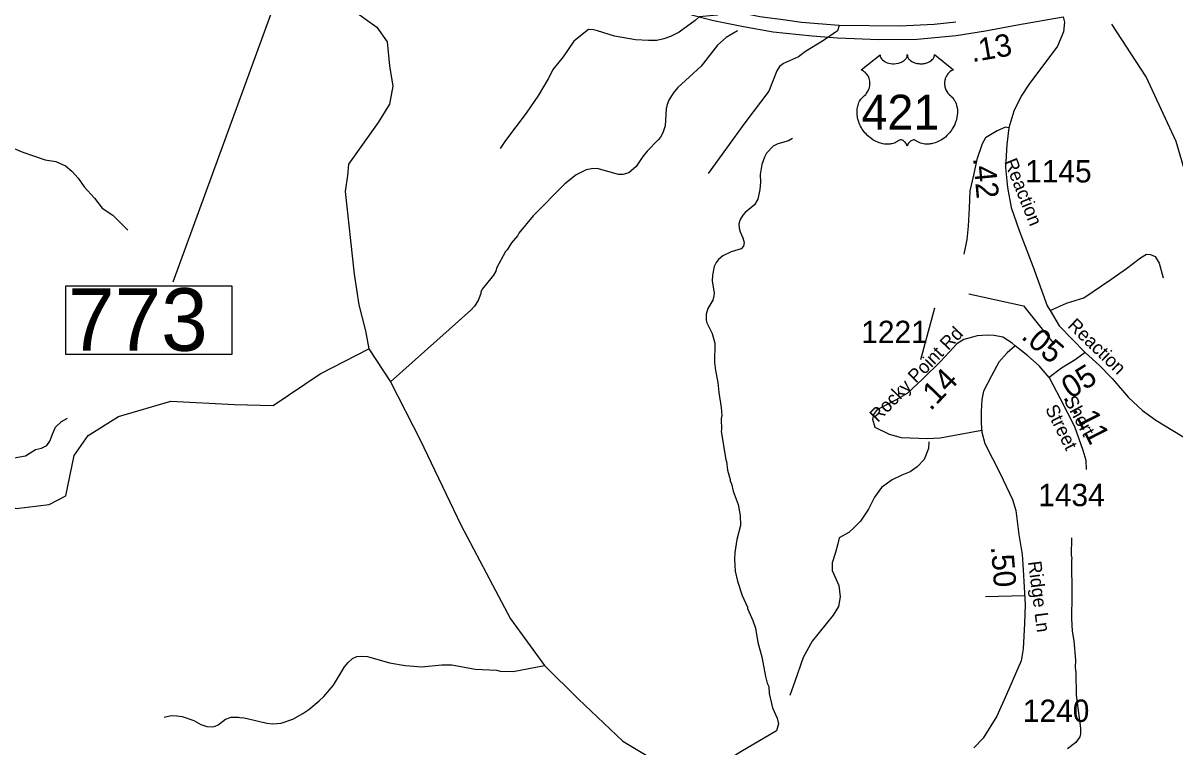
# Model space of a CAD drawing. Extents: x 1248224 to 1454986, y 825081 to 985870.
# Drawn here: x 1318874 to 1325316, y 874747 to 878797 of the extents above; entities that cross this region are included whole.
import ezdxf

# ---------------------------------------------------------------- set-up
doc = ezdxf.new("R2010")
doc.units = 0
for name, color, linetype in [('Exist Hydrographic Creek Single Shore', 7, 'Continuous'), ('Exist Hydrographic Misc Water Feature', 7, 'Continuous'), ('Exist Road Non-System Type 51', 7, 'Continuous'), ('Exist Road Primary US Divided Attributed', 7, 'Continuous'), ('Exist Road Primary US Mileage Hundredths English Label', 7, 'Continuous'), ('Exist Road Primary US Shield CELL', 7, 'Continuous'), ('Exist Road Primary US Shield Number Label', 7, 'Continuous'), ('Exist Road Primary US Structure Standard Bridge Number Label', 7, 'Continuous'), ('Exist Road Secondary Mileage Hundredths English Label', 7, 'Continuous'), ('Exist Road Secondary Type 51 Attributed', 7, 'Continuous'), ('Exist Road Secondary Type 51 Label', 7, 'Continuous'), ('Exist Road Secondary Type 51 Number Label', 7, 'Continuous')]:
    doc.layers.add(name, color=color, linetype=linetype)

msp = doc.modelspace()

# ---------------------------------------------------------------- linework, layer by layer
at = {"layer": 'Exist Hydrographic Creek Single Shore'}
for points in [[(1320702, 878882.3), (1320853.1, 878773.1), (1320910.1, 878690.7), (1320922.8, 878557.6), (1320941.8, 878443.6), (1320922.8, 878342.2), (1320859.4, 878240.8), (1320694.8, 878006.3), (1320688.5, 877942.9), (1320675.8, 877854.2), (1320726.5, 877391.6), (1320751.8, 877220.5), (1320789.8, 877074.8), (1320808.8, 876973.4)], [(1317915.7, 875836.4), (1318052.8, 875653.3), (1318093.1, 875619.5), (1318158.4, 875619.9), (1318214.2, 875632.4), (1318273.4, 875680.1), (1318306.5, 875716.6), (1318323.7, 875746.1), (1318373.8, 875876), (1318346.4, 876153.2), (1318397.4, 876191.7), (1318522.4, 876189.1), (1318836.5, 876081), (1319020.5, 876103.6), (1319113.5, 876151), (1319160.4, 876376.6), (1319238.5, 876489.9), (1319407.4, 876594.8), (1319701.5, 876680.8), (1320056, 876663.3), (1320272.6, 876657), (1320536.5, 876834), (1320808.8, 876973.4)], [(1320808.8, 876973.4), (1320929.1, 876789.6), (1321094.1, 876465.3), (1321322.1, 875990), (1321499.4, 875654.2), (1321600.7, 875464), (1321790.5, 875203.3), (1321980.7, 875014.1), (1322227.6, 874779.7), (1322461.9, 874640.2), (1322537.9, 874589.5), (1322616.2, 874542.5), (1322652.8, 874500.3), (1322683.7, 874370.7), (1322647.2, 874255.2), (1322635.9, 874173.6), (1322644.3, 874072.2), (1322624.6, 873998.9), (1322526.1, 873813), (1322495.2, 873711.7), (1322486.8, 873622.7)]]:
    msp.add_lwpolyline(points, dxfattribs=at)
at = {"layer": 'Exist Hydrographic Misc Water Feature'}
for points in [[(1322869.8, 878753.6), (1322806.6, 878715.5), (1322757.4, 878673), (1322666, 878555.7), (1322536.7, 878435.4), (1322509.8, 878404.2), (1322484.7, 878365), (1322476, 878341.2), (1322471.3, 878317.3), (1322464.6, 878221.5), (1322451.5, 878182), (1322438.8, 878158.4), (1322426.3, 878142.7), (1322364.6, 878080.5), (1322339.7, 878049.2), (1322302.2, 877994.3), (1322261.2, 877959.5), (1322228.9, 877948.5), (1322204.9, 877949.1), (1322085.7, 877982.5), (1322053.7, 877981.5), (1322023.5, 877976.4), (1321966.7, 877948.1), (1321903.2, 877897.9), (1321726.2, 877719.1), (1321647.3, 877621.3), (1321638.9, 877605.7), (1321605.8, 877566.6), (1321580.7, 877527.3), (1321572.5, 877519.5), (1321521.8, 877425.1), (1321517.3, 877409.2), (1321504.7, 877385.5), (1321442.5, 877307.4), (1321434, 877291.6), (1321433.8, 877283.6), (1321418.7, 877244.1), (1321399.7, 877212.7), (1321379.1, 877191.2), (1320929.1, 876789.6)], [(1330314.7, 875138.2), (1330183.7, 875064.7), (1329910.7, 874992), (1329308.7, 874554.3), (1329046.7, 874434.9), (1328873.7, 874490.8), (1328733.7, 874608.5), (1328593.7, 874680.3), (1328418.6, 874683.9), (1328251.6, 874644.5), (1327860.6, 874688.5), (1327736.6, 874756.6), (1327413.6, 875183.3), (1327144.7, 875464.5), (1326872.7, 875604.6), (1326669.5, 875815.4), (1326497.1, 876133.5), (1325856.5, 876718.1), (1325615.6, 877107.1), (1325520.5, 877335.4), (1325422.5, 877797), (1325322.6, 878133.9), (1325155.5, 878495.1), (1324962.5, 878791.1)], [(1323176.9, 878151), (1323154.6, 878137.7), (1323096, 878121.4), (1323069.7, 878108.1), (1323032.6, 878069.2), (1323019.9, 878045.6), (1323004.8, 878006), (1322997.2, 877950.2), (1322997.9, 877906.3), (1322994.8, 877866.4), (1322983.3, 877810.7), (1322964.4, 877779.2), (1322913.1, 877736.8), (1322898.7, 877721.2), (1322884, 877697.6), (1322877.3, 877673.8), (1322878.7, 877649.7), (1322884.1, 877629.6), (1322899.2, 877595.2), (1322906.5, 877569), (1322903.9, 877549.1), (1322889.4, 877533.5), (1322834.9, 877517.1), (1322788.2, 877494.4), (1322763.6, 877473.2), (1322751.2, 877457.5), (1322738.5, 877433.9), (1322729.2, 877386.1), (1322728.3, 877354.2), (1322738.4, 877286), (1322737.9, 877270), (1322731.2, 877246.2), (1322704, 877198.9), (1322695.1, 877167.3), (1322694.1, 877135.3), (1322697.7, 877119.2), (1322728.1, 877060.3), (1322742.5, 877005.9), (1322741.5, 876897.9), (1322746.2, 876853.8), (1322760.4, 876785.4), (1322764.8, 876729.4), (1322778.4, 876645), (1322781.2, 876600.9), (1322778.7, 876585), (1322780.9, 876520.9), (1322778.7, 876513), (1322804.1, 876352.4), (1322807.9, 876344.2), (1322814.6, 876296.1), (1322829.2, 876243.6), (1322828.8, 876235.7), (1322836.4, 876219.4), (1322845.3, 876177.2), (1322873.1, 876102.4), (1322885.4, 876042), (1322885.9, 875986.1), (1322865.7, 875906.7), (1322855.6, 875835), (1322852.5, 875797.1), (1322856.7, 875731), (1322869.1, 875674.7), (1322894.9, 875594), (1322925, 875529.1), (1322924.8, 875521.1), (1322955, 875454.2), (1322969.8, 875411.8), (1322983.6, 875331.4), (1323005.3, 875250.8), (1323026.2, 875140.3), (1323036.2, 875103.7)], [(1324736.8, 875916.5), (1324736, 875820.7), (1324739.4, 875800.6), (1324737.3, 875792.6), (1324739.7, 875596.6), (1324738, 875464.7), (1324742, 875394.6), (1324750.5, 875340.3), (1324759.5, 875232.2), (1324758.4, 875192.2), (1324761.6, 875164.1), (1324763.9, 875036), (1324788.7, 874851.4), (1324787.9, 874819.4), (1324783.4, 874803.6), (1324762.5, 874772.2), (1324715.5, 874735.5)], [(1319662.4, 874913.6), (1319702.6, 874922.4), (1319734.6, 874921.5), (1319764.6, 874916.7), (1319830, 874894.8), (1319869.3, 874871.7), (1319901, 874860.7), (1319933, 874859.8), (1319949.1, 874863.4), (1319965.3, 874870.9), (1320006.2, 874901.7), (1320038.5, 874912.8), (1320078.6, 874913.6), (1320094.5, 874909.1), (1320102.5, 874911), (1320237.7, 874879.1), (1320269.6, 874876.1), (1320317.8, 874880.7), (1320382.4, 874902.9), (1320439.3, 874933.2), (1320472, 874956.2), (1320529.3, 875004.6), (1320556.1, 875029.8), (1320609.8, 875092.2), (1320672.7, 875194.3), (1320691.4, 875219.8), (1320716, 875241.1), (1320740.4, 875252.4), (1320764.5, 875255.7), (1320800.4, 875252.7), (1320923.5, 875217.1), (1321011.1, 875202.5), (1321036.6, 875200.4)], [(1321036.6, 875200.4), (1321102.9, 875195.9), (1321215.3, 875206.6), (1321271.3, 875207.1), (1321402.6, 875181.2), (1321522.6, 875175.8), (1321542.5, 875171.2), (1321614.4, 875169.1), (1321702.9, 875186.6), (1321790.5, 875203.3)], [(1323036.2, 875103.7), (1323044.7, 875085.8), (1323047.5, 875045.7), (1323065.3, 874965.2), (1323091.7, 874908.5), (1323098.8, 874876.3), (1323087.6, 874836.6), (1322889.1, 874719.1), (1322828.1, 874682.7), (1322793.5, 874665.7), (1322750.7, 874644.6), (1322686.4, 874600.8), (1322652.8, 874500.3)]]:
    msp.add_lwpolyline(points, dxfattribs=at)
at = {"layer": 'Exist Road Non-System Type 51'}
msp.add_line((1324257.4, 875588.9), (1324475, 875594.3), dxfattribs=at)
for points in [[(1322787.9, 878873.7), (1322771.3, 878851.6), (1322756.2, 878841.5), (1322656, 878831.5), (1322633.4, 878811.4), (1322543.2, 878746.2), (1322495.5, 878721.1), (1322457.9, 878708.6), (1322417.8, 878698.6), (1322372.7, 878698.6), (1322300, 878703.6), (1322182.2, 878723.6), (1322086.9, 878753.7), (1322064.4, 878758.8), (1322036.8, 878761.3), (1321954.1, 878696), (1321893.9, 878608.2), (1321838.8, 878538), (1321811.2, 878485.3), (1321756.1, 878392.5), (1321688.4, 878292.2), (1321573.1, 878139.2), (1321543, 878094)], [(1323439.1, 878782.9), (1323428.3, 878753.2), (1323350.2, 878699.3), (1323250.5, 878637.3), (1323210, 878607.6), (1323126.5, 878569.9), (1323104.9, 878553.7), (1323088.8, 878529.4), (1323045.6, 878416.1), (1322910.9, 878238.1), (1322706.2, 877955.8)], [(1324387.7, 878210.4), (1324367.9, 878213.3), (1324322.1, 878194.4), (1324257.4, 878154), (1324238.6, 878121.6), (1324208.9, 878032.6), (1324190.1, 877946.3), (1324168.5, 877857.3), (1324165.8, 877760.2), (1324160.4, 877660.4), (1324152.3, 877584.9), (1324136.2, 877504)], [(1318571, 878047.4), (1318601.6, 878069.9), (1318640.4, 878079.6), (1318674.4, 878103.9), (1318710.8, 878128.2), (1318744.8, 878128.2), (1318793.3, 878108.7), (1318873.4, 878074.7), (1318926.8, 878055.3), (1318997.2, 878031), (1319057.8, 878021.3), (1319111.2, 877997), (1319147.6, 877967.9), (1319181.6, 877929), (1319215.6, 877880.4), (1319273.8, 877817.3), (1319317.5, 877761.4), (1319375.8, 877722.5), (1319395.2, 877703.1), (1319460.7, 877637.5)], [(1324618.9, 877189.2), (1324710.2, 877228.9), (1324807.2, 877258.6), (1324958.1, 877361.1), (1325044.3, 877423.1), (1325122.5, 877482.4), (1325157.5, 877504), (1325179.1, 877501.3), (1325206, 877490.5), (1325227.6, 877452.8), (1325249.2, 877371.9)], [(1324235.6, 876517.7), (1324003.3, 876473.8), (1323932, 876470.1), (1323787.6, 876475.6), (1323719.9, 876495.7), (1323639.5, 876534.2), (1323626.7, 876578.1), (1323632.2, 876607.3), (1323654.1, 876636.6), (1323754.7, 876689.7), (1323820, 876725.7)], [(1318390.9, 876472.9), (1318407.5, 876491.4), (1318419.6, 876503.5), (1318436.6, 876508.4), (1318453.6, 876484.1), (1318485.2, 876435.5), (1318519.2, 876406.4), (1318545.8, 876384.5), (1318604.1, 876352.9), (1318672.1, 876326.2), (1318710.9, 876323.8), (1318774, 876340.8), (1318825, 876365.1), (1318888.1, 876374.8), (1318943.9, 876411.2), (1318977.9, 876418.5), (1319007, 876433.1), (1319024, 876457.4), (1319038.5, 876496.2), (1319055.5, 876535.1), (1319089.5, 876566.7), (1319123.5, 876586.1)], [(1323939.4, 876453.6), (1323937.2, 876416.3), (1323913, 876354.3), (1323875.2, 876313.8), (1323834.8, 876286.9), (1323789, 876268), (1323735.1, 876241), (1323675.8, 876197.9), (1323635.4, 876143.9), (1323603.1, 876076.5), (1323557.2, 876009.1), (1323516.8, 875968.6), (1323492.6, 875947), (1323438.7, 875917.4), (1323430.6, 875882.3), (1323417.1, 875833.8), (1323398.2, 875777.1), (1323398.2, 875734), (1323436, 875650.4), (1323444.4, 875587.2), (1323433.6, 875533.2), (1323404, 875484.7), (1323288.1, 875339.1), (1323236.9, 875247.4), (1323191.1, 875112.5), (1323161.4, 875034.3)]]:
    msp.add_lwpolyline(points, dxfattribs=at)
at = {"layer": 'Exist Road Primary US Divided Attributed'}
for points in [[(1324091, 878802.5), (1323969.2, 878789.5), (1323775.6, 878779.7), (1323439.1, 878782.9), (1323227, 878800.7), (1323137.9, 878812.1), (1322995.3, 878831.5), (1322787.9, 878873.7), (1322493.6, 878957.7), (1321917.5, 879163.4), (1321627.4, 879251), (1321223.9, 879358), (1320892.8, 879416.3), (1320516.2, 879456.4)], [(1320503.8, 879387.5), (1320749.3, 879360.5), (1321033, 879319.9), (1321186.1, 879295.1), (1321395.5, 879247.8), (1321602.6, 879191.5), (1321805.2, 879123.9), (1322091.2, 879020.3), (1322307.3, 878943.7), (1322467.2, 878889.7), (1322620.3, 878840.1), (1322735.1, 878810.8), (1322904, 878777.1), (1323068.4, 878747.8), (1323286.8, 878725.2), (1323428.6, 878714), (1323660.5, 878705), (1323874.4, 878707.2), (1324092.8, 878727.5), (1324257.2, 878752.3), (1324435, 878786.1), (1324691.7, 878831.1)]]:
    msp.add_lwpolyline(points, dxfattribs=at)
at = {"layer": 'Exist Road Primary US Shield CELL'}
msp.add_lwpolyline([(1323666.9, 878619.6), (1323667.2, 878615.2), (1323668.3, 878610), (1323669.1, 878607.3), (1323671.6, 878602.2), (1323675.6, 878596.1), (1323681.2, 878590.1), (1323687.5, 878584.9), (1323691.8, 878582.1), (1323699, 878578.2), (1323707.3, 878574.8), (1323716.4, 878572.1), (1323725.8, 878570.3), (1323736, 878569.1), (1323746.1, 878568.9), (1323757, 878569.8), (1323769.1, 878572.1), (1323774.7, 878573.5), (1323780.9, 878575.7), (1323786.7, 878578.1), (1323793, 878581.4), (1323798.1, 878584.7), (1323802.1, 878587.6), (1323807.7, 878593), (1323812.2, 878598.6), (1323814.1, 878601.7), (1323815.7, 878604.7), (1323818, 878611.1), (1323818.6, 878614), (1323819, 878619.9), (1323819.4, 878614.9), (1323819.9, 878611.8), (1323820.7, 878608.8), (1323822, 878605.6), (1323824.2, 878601.1), (1323826.7, 878597.3), (1323831.5, 878591.7), (1323834.4, 878589), (1323837.1, 878586.8), (1323844.4, 878581.8), (1323852.8, 878577.5), (1323856.9, 878575.7), (1323861.2, 878574.2), (1323866.6, 878572.6), (1323872.2, 878571.3), (1323877.7, 878570.3), (1323883.4, 878569.5), (1323889.1, 878569.1), (1323893.8, 878568.9), (1323899.6, 878569), (1323905, 878569.3), (1323910.4, 878569.9), (1323916.4, 878571), (1323921.3, 878572), (1323927.7, 878573.7), (1323933.5, 878575.8), (1323938.5, 878578), (1323945.1, 878581.4), (1323950.5, 878584.8), (1323954.4, 878587.9), (1323959, 878592.2), (1323963.4, 878597.3), (1323966, 878601), (1323967.8, 878604.8), (1323969.5, 878608.8), (1323970.5, 878613.1), (1323971, 878616.8), (1323971.1, 878620), (1324077.4, 878535.3), (1324074.9, 878534.3), (1324069.1, 878531.5), (1324064.5, 878528.8), (1324057.2, 878523.7), (1324054.1, 878520.8), (1324050.9, 878517.9), (1324048.1, 878514.7), (1324045.5, 878511.8), (1324042.4, 878507.5), (1324039.7, 878503.3), (1324037, 878498.5), (1324035, 878494.5), (1324031.7, 878485.9), (1324030.2, 878480.5), (1324029.2, 878475.9), (1324027.9, 878466.5), (1324027.6, 878461.9), (1324027.6, 878457.5), (1324027.9, 878452.8), (1324028.3, 878448.2), (1324029.1, 878443.5), (1324029.9, 878439.4), (1324031.2, 878434.3), (1324033.1, 878428.4), (1324035.4, 878422.7), (1324040.2, 878413.5), (1324046.5, 878404), (1324050.9, 878398.8), (1324055.3, 878394.2), (1324061.9, 878388.7), (1324065.4, 878385.6), (1324069.5, 878381.5), (1324076.2, 878373.8), (1324078.9, 878370.1), (1324081.6, 878366), (1324084.1, 878361.8), (1324086.6, 878357.3), (1324088.6, 878353.4), (1324092.4, 878344.2), (1324095.1, 878335.4), (1324096.4, 878330.7), (1324098.3, 878320.3), (1324099.1, 878315.2), (1324099.9, 878305), (1324099.9, 878292.7), (1324099, 878281), (1324096.8, 878267.4), (1324095, 878259.2), (1324092.2, 878249.7), (1324089.5, 878241.5), (1324084.6, 878229.4), (1324080.3, 878220.6), (1324074.7, 878210.3), (1324070.9, 878204.1), (1324066.5, 878197.4), (1324060.9, 878189.8), (1324054.3, 878181.6), (1324046.5, 878173), (1324040.2, 878166.7), (1324031.9, 878159.2), (1324026.8, 878155.1), (1324019.7, 878149.7), (1324009.9, 878143.2), (1324000.2, 878137.6), (1323992, 878133.4), (1323984.7, 878130.2), (1323975.3, 878126.6), (1323959.6, 878122.3), (1323953.9, 878121.1), (1323947.1, 878120.1), (1323940.8, 878119.5), (1323934.6, 878119.1), (1323926.4, 878119.1), (1323918.1, 878119.7), (1323910.4, 878120.9), (1323902.3, 878122.6), (1323893.8, 878125.1), (1323886.1, 878128.1), (1323878.3, 878131.9), (1323865.2, 878140.2), (1323861.4, 878142.2), (1323859.2, 878142.8), (1323854.1, 878143), (1323849.4, 878142), (1323844.5, 878140.1), (1323841.5, 878138.5), (1323837.6, 878135.9), (1323834.6, 878133.6), (1323831, 878130.1), (1323828.4, 878127.2), (1323826.5, 878125), (1323822.8, 878119.1), (1323821.5, 878116.4), (1323820.1, 878112.8), (1323818.9, 878107.5), (1323817.2, 878114.2), (1323815.3, 878118.5), (1323813, 878122.3), (1323810.7, 878125.6), (1323807, 878129.9), (1323803.6, 878133.1), (1323799.6, 878136.4), (1323795.4, 878139), (1323791.9, 878140.7), (1323788.8, 878141.9), (1323785, 878142.9), (1323781.8, 878143.1), (1323779.3, 878143), (1323775.7, 878142.2), (1323770.9, 878138.8), (1323766.4, 878135.6), (1323761.4, 878132.6), (1323755.5, 878129.4), (1323751.2, 878127.4), (1323746, 878125.4), (1323740, 878123.4), (1323733.5, 878121.7), (1323726.8, 878120.4), (1323720.9, 878119.4), (1323714.5, 878118.9), (1323708.8, 878118.7), (1323702.8, 878118.7), (1323697.3, 878119.2), (1323690.8, 878119.7), (1323682.8, 878120.9), (1323676.1, 878122.4), (1323669.1, 878124.3), (1323661.9, 878126.6), (1323654.1, 878129.5), (1323644.5, 878133.7), (1323637.8, 878137.2), (1323627.2, 878143.3), (1323614.7, 878151.9), (1323605.3, 878159.5), (1323598.5, 878165.7), (1323588.4, 878176), (1323582.4, 878182.7), (1323573.1, 878194.8), (1323567.1, 878203.5), (1323563.3, 878209.9), (1323557.6, 878220.2), (1323554.5, 878226.7), (1323550.5, 878236.1), (1323547.3, 878244.7), (1323544.7, 878252.9), (1323543.3, 878258.1), (1323541.3, 878267.2), (1323540.1, 878273.7), (1323538.9, 878282.5), (1323538.2, 878291.9), (1323538.1, 878300.5), (1323538.3, 878307.6), (1323539.1, 878316), (1323540.5, 878324.8), (1323542.2, 878332.4), (1323543.8, 878337.9), (1323546, 878344.6), (1323549, 878351.9), (1323552.5, 878358.9), (1323555.9, 878364.8), (1323560.1, 878371.1), (1323564.2, 878376.4), (1323569.7, 878382.3), (1323575.3, 878387.7), (1323580.5, 878391.9), (1323586.6, 878397.9), (1323589.8, 878401.6), (1323593.7, 878406.7), (1323596.8, 878411.4), (1323599.2, 878415.6), (1323602.5, 878421.8), (1323604.4, 878426.4), (1323606.9, 878433.6), (1323608.1, 878438.6), (1323609.3, 878445.1), (1323610.1, 878451.2), (1323610.5, 878458.8), (1323610.3, 878465.1), (1323609.5, 878472.4), (1323608.1, 878479.5), (1323606.4, 878485.6), (1323603.8, 878492.6), (1323601.4, 878497.8), (1323597.3, 878504.8), (1323592.8, 878511.2), (1323588.1, 878516.5), (1323583.4, 878521.2), (1323578.9, 878524.7), (1323574.6, 878527.8), (1323569.2, 878531.1), (1323563.9, 878533.6), (1323560.7, 878535)], close=True, dxfattribs=at)
at = {"layer": 'Exist Road Primary US Structure Standard Bridge Number Label'}
msp.add_line((1320423, 879294.9), (1319712.2, 877346.4), dxfattribs=at)
msp.add_lwpolyline([(1319113.2, 877327.4), (1320042.2, 877327.4), (1320042.2, 876943.3), (1319113.2, 876943.3)], close=True, dxfattribs=at)
at = {"layer": 'Exist Road Secondary Type 51 Attributed'}
for points in [[(1324691.7, 878831.1), (1324697.8, 878801.8), (1324692.6, 878746.7), (1324658.5, 878668), (1324499.6, 878453.2), (1324456, 878387.7), (1324415.7, 878303.4), (1324387.7, 878210.4), (1324375.4, 878117.4), (1324368.4, 877989.3), (1324378.9, 877876.2), (1324400, 877765.6), (1324445.6, 877635.8), (1324521, 877435.7), (1324601.4, 877215.5), (1324618.9, 877189.2), (1324668, 877103.2), (1324813.2, 876952.9)], [(1324422.5, 876990.9), (1324406.4, 877006), (1324353.8, 877038.5), (1324305.6, 877048.5), (1324267.1, 877050.3), (1324209.2, 877046.8), (1324182.9, 877039.8), (1324135.6, 877025.7), (1324097, 877001.2), (1324053.1, 876955.5), (1324004.1, 876902.9), (1323905.9, 876806.4), (1323820, 876725.7)], [(1324422.5, 876990.9), (1324377.1, 876952.2), (1324331.5, 876899.5), (1324289.5, 876822.3), (1324245.6, 876736.4), (1324235.1, 876690.7), (1324231.6, 876624.1), (1324231.6, 876559.1), (1324236.9, 876508.2), (1324252.6, 876445.1), (1324338.5, 876276.6), (1324406.7, 876130.6), (1324425.9, 876069.2), (1324443.5, 875935.8), (1324461, 875823.5), (1324468, 875737.6), (1324478.5, 875544.5), (1324475, 875436.8), (1324468, 875296.4), (1324455.7, 875227.9), (1324373.3, 875040.2), (1324319.1, 874919.8), (1324243.7, 874795.2), (1324191.1, 874742.5)], [(1324613.3, 876814.3), (1324557.5, 876878.6), (1324492.6, 876934.8), (1324422.5, 876990.9)], [(1324813.2, 876952.9), (1324757.1, 876912.6), (1324681.7, 876865.2), (1324613.3, 876814.3)], [(1324813.2, 876952.9), (1324893.9, 876881), (1324965.7, 876807.3), (1325056.9, 876702), (1325134.1, 876628.3), (1325209.5, 876575.7), (1325400.1, 876458.9), (1325470.2, 876402.7), (1325552.6, 876318.5), (1325652.5, 876207.9), (1325748.4, 876096), (1325836.4, 875991), (1325999.4, 875815.5), (1326241.1, 875595), (1326456.8, 875384.5)], [(1324613.3, 876814.3), (1324675, 876696.1), (1324753.9, 876540), (1324801.2, 876406.6), (1324817, 876352.2), (1324819.4, 876298.8)]]:
    msp.add_lwpolyline(points, dxfattribs=at)
at = {"layer": 'Exist Road Secondary Type 51 Label'}
for points in [[(1324163.6, 877281.5), (1324468.7, 877214.8), (1324640.5, 877000.7)], [(1323970.7, 877200.8), (1323893.6, 876913)]]:
    msp.add_lwpolyline(points, dxfattribs=at)

# ---------------------------------------------------------------- texts
at = {"layer": 'Exist Road Primary US Mileage Hundredths English Label'}
msp.add_text('.13', height=125, rotation=9.9001, dxfattribs=at).set_placement((1324182.6, 878577.3))
at = {"layer": 'Exist Road Primary US Shield Number Label'}
msp.add_text('421', height=195, dxfattribs=at).set_placement((1323563.1, 878200.9))
at = {"layer": 'Exist Road Primary US Structure Standard Bridge Number Label'}
msp.add_text('773', height=350, dxfattribs=at).set_placement((1319125.8, 876963))
at = {"layer": 'Exist Road Secondary Mileage Hundredths English Label'}
for s, rotation, p in [('.42', 275.33201, (1324186.6, 878041.3)), ('.05', 319.12174, (1324451, 877035.9)), ('.05', 32.14575, (1324693.1, 876666.6)), ('.14', 46.14561, (1323949.4, 876623.3)), ('.11', 296.8036, (1324740.2, 876636.2)), ('.50', 274.66334, (1324286.3, 875867.1))]:
    msp.add_text(s, height=125, rotation=rotation, dxfattribs=at).set_placement(p)
at = {"layer": 'Exist Road Secondary Type 51 Label'}
for s, rotation, p in [('Reaction', 291.81434, (1324359.6, 878021.9)), ('Reaction', 316.26363, (1324711.1, 877097.9)), ('Rocky Point Rd', 45.68999, (1323654, 876559)), ('Short', 298.42057, (1324692.5, 876687.3)), ('Street', 296.54385, (1324588.4, 876639.3)), ('Ridge Ln', 277.356, (1324493.7, 875782.7))]:
    msp.add_text(s, height=75, rotation=rotation, dxfattribs=at).set_placement(p)
at = {"layer": 'Exist Road Secondary Type 51 Number Label'}
for s, p in [('1145', (1324478.2, 877904.8)), ('1221', (1323561.7, 877006.2)), ('1434', (1324551.4, 876093.9)), ('1240', (1324465.5, 874886.9))]:
    msp.add_text(s, height=125, dxfattribs=at).set_placement(p)

doc.saveas('drawing.dxf')
